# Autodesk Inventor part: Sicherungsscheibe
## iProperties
Created: 2005-12
Part Number: Sicherungsscheibe
Document SubType Name: Modeling
Designer: Kumpf
Manufacturer: Standard
Standards Organization: Custom
Author: Kumpf
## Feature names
1. Extrusion1
2. Bohrung1 [Hole]
3. Rundung1 [Fillet]
